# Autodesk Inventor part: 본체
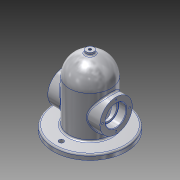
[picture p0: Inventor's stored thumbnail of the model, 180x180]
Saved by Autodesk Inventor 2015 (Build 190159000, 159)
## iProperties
Created: 2019-11
Part Number: 본체
Material: 알루미늄 6061
Document SubType Name: Modeling
Designer: Lineart
Density: 2.7 g/cm^3
Appearance: 알루미늄 - 평지
Mass: 1106.52 g
Surface Area: 886.269 cm^2
Volume: 409.823 cm^3
Author: Lineart
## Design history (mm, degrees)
sketch "스케치1"
  geometry: C1 r 70 at (0, 0); 1 further point
  constraints: 1 centre point, 1 coincident
  dimensions: "d0" = 70 radius of C1
extrude "돌출1" new body sketch "스케치1" distance "d1" = 10; taper "d2" = 0 deg
sketch "스케치2"
  geometry: C1 r 40 at (0, 0); 1 further point
  constraints: 1 centre point, 1 coincident
  dimensions: "d3" = 40 radius of C1
extrude "돌출2" join sketch "스케치2" distance "d4" = 80; taper "d5" = 0 deg
sketch "스케치3"
  geometry: L1 (40, 90)-(-40, 90) reference; L2 (0, 130)-(0, 90); L3 (40, 90)-(0, 90); A1 r 40 centre (0, 90) between (40, 90) and (0, 130); 1 further point
  constraints: 4 end point, 2 point on circle, 1 centre point, 1 collinear, 1 midpoint, 1 vertical
revolve "회전1" sketch "스케치3" stored, may be unused: angle "d6" = 90 deg
node "작업 평면1"
sketch "스케치4"
  geometry: C1 r 7.5 at (0, 0); 1 further point
  constraints: 1 centre point, 1 coincident
  dimensions: "d8" = 7.5 radius of C1
extrude "돌출3" join sketch "스케치4" distance "d9" = 45; taper "d10" = 0 deg
sketch "스케치5"
  geometry: C1 r 70 at (0, 0) reference; 3 further points
  constraints: 2 vertical alignment
  dimensions: "d11" = 55 distance of point (0, 0) point (0, 55); "d12" = 110 distance of point (0, -55) point (0, 55)
hole "구멍1" sketch "스케치5" at (0, 55), (0, -55) diameter "d13" = 9; stored, may be unused: countersink angle "d17" = 90 deg, drill point angle "d19" = 118 deg; dims "d14" = 6, "d15" = 4, "d16" = 2, "d18" = 8
sketch "스케치6"
  geometry: C1 r 7.5 at (0, 0) reference; C2 r 30 at (0, 0); 1 further point
  constraints: 1 centre point, 1 coincident
  dimensions: "d20" = 30 radius of C2
extrude "돌출4" cut sketch "스케치6" distance "d21" = 90; taper "d22" = 0 deg
sketch "스케치7"
  geometry: L1 (30, 90)-(-30, 90) reference; L2 (-30, 90)-(0, 90); L3 (0, 120)-(0, 90); A1 r 30 centre (0, 90) between (0, 120) and (-30, 90); 1 further point
  constraints: 4 end point, 2 point on circle, 1 centre point, 1 collinear, 1 midpoint, 1 perpendicular
revolve "회전2" sketch "스케치7" stored, may be unused: angle "d23" = 90 deg
sketch "스케치8"
  geometry: L1 (40, 90)-(-40, 90) reference; L2 (-40, 10)-(40, 10) reference; L3 (40, 10)-(40, 90) reference; L4 (-40, 10)-(-40, 90) reference; C1 r 31 at (0, 50); 1 further point
  constraints: 1 centre point
  dimensions: "d24" = 31 radius of C1; "d25" = 50 distance of point (0, 0) C1.centre; "d26" = 40 distance from line of L3 C1.centre
extrude "돌출5" join sketch "스케치8" stored distance "d27" = 100; taper "d28" = 0 deg
sketch "스케치9"
  geometry: C1 r 31 at (0, 0) reference; C2 r 20 at (0, 0); 1 further point
  constraints: 1 centre point, 1 coincident
  dimensions: "d29" = 20 radius of C2
extrude "돌출6" cut sketch "스케치9" distance "d30" = 15; taper "d31" = 0 deg
sketch "스케치10"
  geometry: C1 r 31 at (0, 0) reference; C2 r 16.5 at (0, 0); 1 further point
  constraints: 1 centre point, 1 coincident
  dimensions: "d32" = 16.5 radius of C2
extrude "돌출7" cut sketch "스케치10" distance "d33" = 35; taper "d34" = 0 deg
sketch "스케치11"
  geometry: C1 r 30 at (0, 0) reference; 1 further point
extrude "돌출8" cut sketch "스케치11" distance "d35" = 90; taper "d36" = 0 deg
sketch "스케치12"
  geometry: C1 r 7.5 at (0, 0) reference; 2 further points
  constraints: 1 coincident
hole "구멍2" sketch "스케치12" at (0, 0) diameter "d37" = 5.188; stored, may be unused: countersink angle "d41" = 90 deg, drill point angle "d43" = 118 deg; dims "d38" = 30, "d39" = 4, "d40" = 2, "d42" = 16
sketch "스케치13"
  geometry: L1 (-40, 40)-(-40, -40) reference; L2 (40, -40)-(40, 40) reference; L3 (40, 40)-(-40, 40) reference; L4 (40, -40)-(-40, -40) reference; L5 (50, 70)-(40, 70) reference; C1 r 31 at (0, 0) reference; 7 further points
  constraints: 7 other
  dimensions: "d44" = 26 distance of point (-26, 0) C1.centre; "d45" = 40 distance from line of L3 point (-26, 0); "d48" = 360 deg dimension on C1.centre point (-26, 0) (derived)
hole "구멍3" sketch "스케치13" at (-26, 0), (0, -26), (26, 0), (0, 26) diameter "d50" = 3.242; stored, may be unused: countersink angle "d54" = 90 deg, drill point angle "d56" = 118 deg; dims "d51" = 8, "d52" = 4, "d53" = 2, "d55" = 10
fillet "모깎기1" dims "d57" = 3, "d62" = 0.3
node "작업 평면2"
sketch "스케치14"
  geometry: L1 (-70, -10)-(70, -10) reference; L2 (50, 9)-(50, 71) reference; 2 further points
  constraints: 1 other
  dimensions: "d58" = 50 distance from line of L1 point (0, 40); "d59" = 50 distance from line of L2 point (0, 40)
feature "엠보싱1" sketch "스케치14" dims "d1" = 10, "d2" = 0, "d60" = 0.5, "d61" = 0
chamfer "모따기1" distance "d63" = 1; stored, may be unused: second distance "d64" = 2, angle "d65" = 45 deg
chamfer "모따기2" distance "d66" = 1; stored, may be unused: second distance "d67" = 2, angle "d68" = 45 deg
node "솔리드1"
mirror "대칭1"
mirror "대칭2"
node "투영된 루프1"
node "투영된 루프2"
node "투영된 루프3"
